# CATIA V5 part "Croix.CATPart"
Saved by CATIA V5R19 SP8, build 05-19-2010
Part number: Croix
Bounding box of the stored display mesh (mm): x -8.038 to 8.038, y -8.038 to 8.038, z -5.5 to 1.5
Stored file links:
  D:\Travail\1 - ITEC_Turgot\00 - TP en cours de préparration\TP 4-9.2d Imprim3D_Uprint\Diviseur\Croix.CATPart
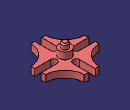
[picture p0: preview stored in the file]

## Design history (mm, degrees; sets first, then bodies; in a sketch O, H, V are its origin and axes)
Body1 (main body)
  Sketch1 on yz-plane, origin (0, 0, 0), H (0, 1, 0), V (0, 0, 1)
    axis line L1 (0, -5.9437) -> (0, 7.5117)
    point P1 (0, -5.9437)
    point P3 (0, 1.5)
    line L2 (0, 1.5) -> (-1, 1.5)
    line L3 (-1, 1.5) -> (-1, 0)
    line L4 (-1, 0) -> (-1.75, 0)
    line L5 (-1.75, 0) -> (-1.75, -2)
    line L6 (-1, -4) -> (-1, -5.5)
    line L7 (-1, -5.5) -> (0, -5.5)
    point P9 (0, -5.5)
    line L8 (-1, -4) -> (-8.1, -4)
    line L9 (-8.1, -4) -> (-8.1, -2)
    line L10 (-8.1, -2) -> (-1.75, -2)
    reference intersected line E1 through (0, 0) direction (-1, 0) from xy-plane
    "Radius" L3 L1 = 1
    distance L2 L4 = 1.5
    "Radius" L5 L1 = 1.75
    distance L4 L10 = 2
    distance L10 L8 = 2
    distance L7 L8 = 1.5
    "Radius" L9 L1 = 8.1
    coincidence: P1 V, P3 L1, P9 L1, L6 L3, L4 E1
    vertical: L1 V, L3 V, L5 V, L9 V
    horizontal: L2 H, L4 H, L10 H
  Shaft1: profile Sketch1, axis Sketch1.L1, angle 360
  Chamfer1: length 0.3, angle 45, on edge [face of Shaft1 from Sketch1.L7 | face of Shaft1 from Sketch1.L6]; edge [face of Shaft1 from Sketch1.L3 | face of Shaft1 from Sketch1.L2]
  Sketch2 on face of Shaft1 from Sketch1.L8, origin (0, 0, -4), H (1, 0, 0), V (0, -1, 0)
    construction line L1 (0, 3.368) -> (0, 8.1)
    point P1 (0, 3.368)
    point P2 (0, 8.1)
    line L2 (-1, 3.368) -> (-1, 8.1)
    line L3 (1, 8.1) -> (1, 3.368)
    arc A1 centre (0, 8.1) radius 1 from (-1, 8.1) to (1, 8.1) cw
    arc A2 centre (0, 3.368) radius 1 from (1, 3.368) to (-1, 3.368) cw
    circle A3 centre (8.1317, 8.1317) radius 5.97
    point P7 (8.1317, 8.1317)
    axis line L4 (0, 0) -> (8.1317, 8.1317)
    reference projected point E1 (0, 0) from axis of face of Shaft1 from Sketch1.L6
    reference projected circle E2 centre (0, 0) radius 8.1 from edge [face of Shaft1 from Sketch1.L8 | face of Shaft1 from Sketch1.L9]
    reference projected point E3 (0, 0) from axis of face of Shaft1 from Sketch1.L6
    distance L1 L2 = 1
    angle L4 H = 45
    distance P1 E1 = 3.368
    radius A3 = 5.97
    distance P7 E3 = 11.5
    coincidence: P1 V, P2 E2
    vertical: L1 V
    tangency: A1 L2, A2 L2, A1 L3, A2 L3
  Pocket1: profile Sketch2, direction (0, 0, 1), through (limit type 3)
  CircPattern1: of Pocket1, instances 4, angular step 90 {= 360.0*1 deg/CircPattern1.AngularNumber}, axis from face of Shaft1 from Sketch1.L6
  Sketch3 on face of Shaft1 from Sketch1.L8, origin (0, 0, -4), H (1, 0, 0), V (0, -1, 0)
    construction circle A1 centre (0, 0) radius 2.9919
    polyline C1
    polyline C2
    polyline C3
    polyline C4
    polyline C5
  Pocket2: profile Sketch3, direction (0, 0, 1), length 0.5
